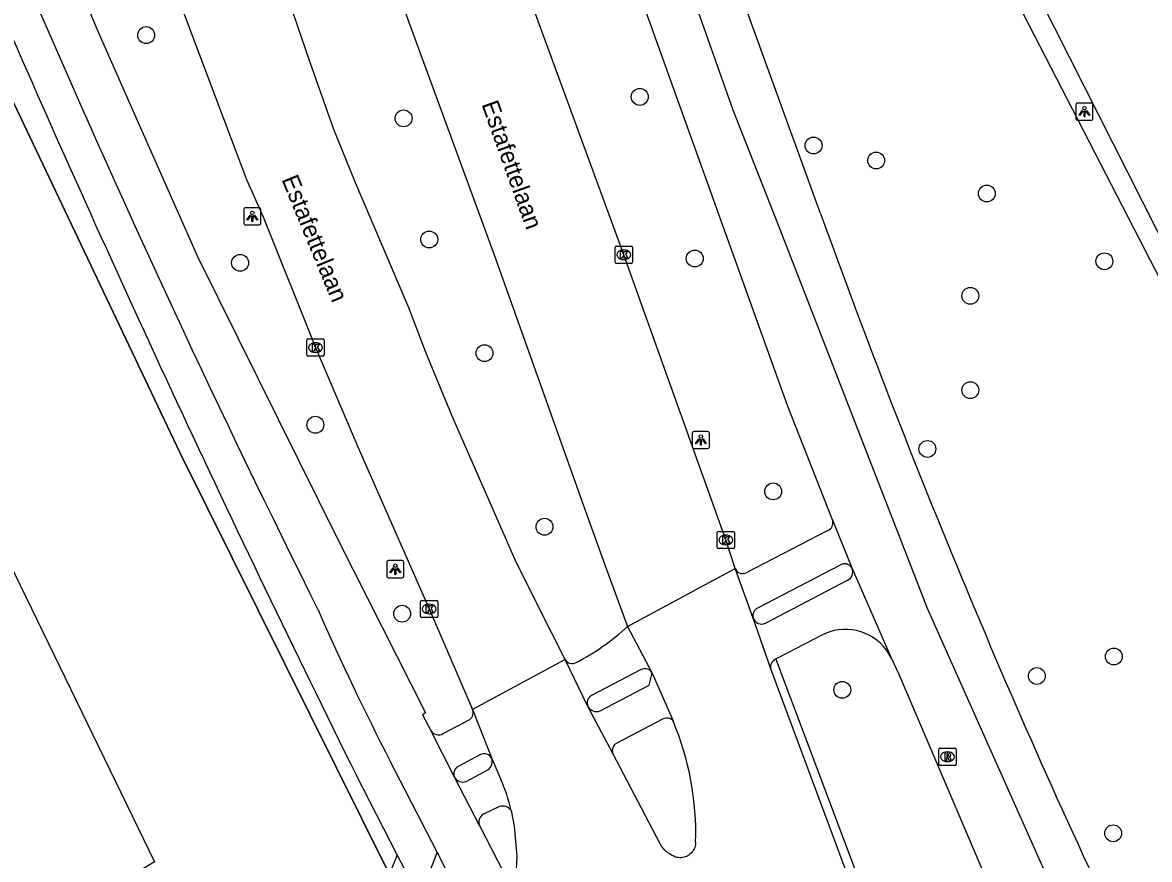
# Model space of a CAD drawing. Extents: x 158838 to 160074, y 386376 to 387776.
# Drawn here: x 159123.5 to 159188.9, y 387277.8 to 387326.4 of the extents above; entities that cross this region are included whole.
import ezdxf

# ---------------------------------------------------------------- set-up
doc = ezdxf.new("R2010")
doc.units = 0
for name, color, linetype in [('IMGEO_Berm_open', 7, 'Continuous'), ('IMGEO_Boom', 7, 'Continuous'), ('IMGEO_Fietspad_gesloten', 7, 'Continuous'), ('IMGEO_Fietspad_open', 7, 'Continuous'), ('IMGEO_Groenvoorziening', 7, 'Continuous'), ('IMGEO_Hek', 7, 'Continuous'), ('IMGEO_Kolk', 7, 'Continuous'), ('IMGEO_Lichtpunt', 7, 'Continuous'), ('IMGEO_Openbare_ruimte_label', 7, 'Continuous'), ('IMGEO_Pand', 7, 'Continuous'), ('IMGEO_Parkeervlak_open', 7, 'Continuous'), ('IMGEO_Rijbaan_lokaal_gesloten', 7, 'Continuous'), ('IMGEO_Rioolput', 7, 'Continuous'), ('IMGEO_Voetpad_open', 7, 'Continuous')]:
    doc.layers.add(name, color=color, linetype=linetype)

msp = doc.modelspace()

# ---------------------------------------------------------------- linework, layer by layer
at = {"layer": 'IMGEO_Berm_open'}
msp.add_lwpolyline([(159167.198, 387289.45), (159172.7, 387274.857), (159175.747, 387267.87), (159176.718, 387265.825)], dxfattribs=at)
at = {"layer": 'IMGEO_Boom'}
for centre in [(159130.664, 387325.65), (159159.305, 387322.064), (159145.602, 387320.82), (159169.392, 387319.247), (159173.022, 387318.377), (159179.442, 387316.459), (159147.091, 387313.791), (159162.497, 387312.694), (159136.116, 387312.438), (159186.266, 387312.53), (159178.486, 387310.527), (159150.299, 387307.198), (159178.485, 387305.053), (159140.484, 387303.049), (159175.995, 387301.643), (159167.05, 387299.183), (159153.779, 387297.133), (159145.522, 387292.089), (159186.812, 387289.608), (159182.349, 387288.476), (159171.057, 387287.673), (159186.773, 387279.351)]:
    msp.add_circle(centre, 0.489, dxfattribs=at)
at = {"layer": 'IMGEO_Fietspad_gesloten'}
for points in [[(159128.072, 387325.399), (159129.745, 387321.615), (159133.641, 387312.8), (159141.817, 387296.315), (159146.881, 387286.339), (159146.705, 387286.224), (159147.177, 387285.324)], [(159148.556, 387282.605), (159147.177, 387285.324)], [(159147.553, 387278.26), (159144.821, 387283.538)], [(159150.028, 387279.772), (159148.556, 387282.605)], [(159150.028, 387279.772), (159151.416, 387277.056)], [(159149.276, 387274.84), (159147.553, 387278.26)]]:
    msp.add_lwpolyline(points, dxfattribs=at)
for centre, radius, start, end in [((159873.922, 387646.377), 811.985, 201.113346, 203.284745), ((159777.701, 387609.871), 711.825, 203.409054, 206.499215), ((159287.82, 387357.075), 160.799, 203.76888, 207.21437)]:
    msp.add_arc(centre, radius, start, end, dxfattribs=at)
at = {"layer": 'IMGEO_Fietspad_open'}
for points in [[(159241.987, 387161.499), (159241.072, 387163.276), (159239.654, 387165.944), (159224.192, 387195.365), (159212.826, 387217.468), (159196.082, 387250), (159193.579, 387254.862), (159185.609, 387270.852), (159175.995, 387292.396), (159167.405, 387314.468), (159164.73, 387321.295), (159159.918, 387334.918), (159154.676, 387349.669), (159151.45, 387360.212), (159147.299, 387371.842)], [(159144.238, 387370.749), (159148.463, 387357.842), (159156.056, 387337.038), (159167.867, 387304.177), (159170.435, 387297.651), (159170.503, 387297.478)], [(159170.503, 387297.478), (159171.628, 387294.708)], [(159171.628, 387294.708), (159173.892, 387289.524)], [(159166.597, 387291.535), (159171.36, 387294.036)], [(159173.892, 387289.524), (159173.766, 387289.756), (159173.62, 387289.975), (159173.455, 387290.181), (159173.272, 387290.371), (159173.072, 387290.544), (159172.859, 387290.699), (159172.632, 387290.833), (159172.394, 387290.947), (159172.147, 387291.04), (159171.892, 387291.11), (159171.633, 387291.156), (159171.37, 387291.18), (159171.106, 387291.18), (159170.843, 387291.156), (159170.584, 387291.109), (159170.329, 387291.039), (159170.082, 387290.946), (159169.865, 387290.843), (159167.291, 387289.506), (159167.198, 387289.45)], [(159173.892, 387289.524), (159174.345, 387288.581), (159180.896, 387273.22), (159181.018, 387272.967), (159181.489, 387272.084), (159181.659, 387271.751)], [(159157.017, 387286.449), (159159.853, 387287.936), (159160.03, 387288.647)], [(159160.657, 387285.983), (159157.971, 387284.588)], [(159149.241, 387282.364), (159150.495, 387283.037)], [(159151.169, 387280.904), (159150.233, 387280.461)], [(159147.553, 387278.26), (159146.53, 387275.631)]]:
    msp.add_lwpolyline(points, dxfattribs=at)
for centre, radius, start, end in [((159171.144, 387294.512), 0.523, 294.46206, 22.05277), ((159166.38, 387292.005), 0.517, 200.20704, 294.76202), ((159167.356, 387289.014), 0.463, 109.88328, 195.85048), ((159156.814, 387287.018), 0.604, 210.6401, 289.61048), ((159160.878, 387285.576), 0.463, 39.13364, 118.43654), ((159158.231, 387284.136), 0.521, 119.88382, 197.58793), ((159150.174, 387283.511), 0.573, 304.08031, 18.26313), ((159149.039, 387282.885), 0.559, 210.07468, 291.15904), ((159150.494, 387280.008), 0.522, 119.94595, 206.91513), ((159151.351, 387280.344), 0.589, 34.67443, 108.04385)]:
    msp.add_arc(centre, radius, start, end, dxfattribs=at)
at = {"layer": 'IMGEO_Groenvoorziening'}
for points in [[(159224.36, 387402.222), (159224.03, 387402.865), (159159.729, 387369.196), (159208.786, 387274.075), (159201.998, 387269.928), (159255.258, 387166.205), (159257.42, 387167.319)], [(159271.465, 387305.683), (159209.686, 387274.058), (159161.319, 387369.689), (159224.36, 387402.222)]]:
    msp.add_lwpolyline(points, dxfattribs=at)
at = {"layer": 'IMGEO_Hek'}
for points in [[(159224.03, 387402.865), (159159.729, 387369.196), (159208.786, 387274.075), (159201.998, 387269.928), (159255.258, 387166.205), (159257.42, 387167.319)], [(159111.223, 387350.914), (159120.947, 387325.983), (159132.639, 387301.404), (159144.696, 387277.152), (159141.337, 387268.603), (159136.701, 387264.574), (159101.97, 387242.767)]]:
    msp.add_lwpolyline(points, dxfattribs=at)
at = {"layer": 'IMGEO_Kolk'}
for p, q in [((159157.877, 387312.485), (159157.877, 387313.337)), ((159157.952, 387313.411), (159158.804, 387313.411)), ((159158.365, 387313.191), (159158.39, 387313.191)), ((159158.878, 387313.337), (159158.878, 387312.485)), ((159158.388, 387312.631), (159158.363, 387312.631)), ((159158.804, 387312.411), (159157.952, 387312.411)), ((159139.992, 387307.1), (159139.992, 387307.952)), ((159140.067, 387308.026), (159140.919, 387308.026)), ((159140.993, 387307.952), (159140.993, 387307.1)), ((159140.48, 387307.806), (159140.505, 387307.806)), ((159140.919, 387307.026), (159140.067, 387307.026)), ((159140.503, 387307.246), (159140.478, 387307.246)), ((159163.798, 387295.94), (159163.798, 387296.792)), ((159163.873, 387296.866), (159164.725, 387296.866)), ((159164.799, 387296.792), (159164.799, 387295.94)), ((159164.286, 387296.646), (159164.311, 387296.646)), ((159164.725, 387295.866), (159163.873, 387295.866)), ((159164.309, 387296.086), (159164.284, 387296.086)), ((159146.583, 387291.935), (159146.583, 387292.787)), ((159146.658, 387292.861), (159147.51, 387292.861)), ((159147.071, 387292.641), (159147.096, 387292.641)), ((159147.584, 387292.787), (159147.584, 387291.935)), ((159147.51, 387291.861), (159146.658, 387291.861)), ((159147.094, 387292.081), (159147.069, 387292.081))]:
    msp.add_line(p, q, dxfattribs=at)
for points in [[(159157.877, 387312.485), (159157.877, 387313.337)], [(159157.952, 387313.411), (159158.804, 387313.411)], [(159158.878, 387313.337), (159158.878, 387312.485)], [(159158.198, 387313.111), (159158.321, 387313.111), (159158.321, 387312.96), (159158.451, 387313.111), (159158.615, 387313.111), (159158.469, 387312.96), (159158.622, 387312.711), (159158.47, 387312.711), (159158.385, 387312.875), (159158.321, 387312.808), (159158.321, 387312.711), (159158.198, 387312.711), (159158.198, 387313.111)], [(159158.804, 387312.411), (159157.952, 387312.411)], [(159139.992, 387307.1), (159139.992, 387307.952)], [(159140.067, 387308.026), (159140.919, 387308.026)], [(159140.993, 387307.952), (159140.993, 387307.1)], [(159140.313, 387307.726), (159140.436, 387307.726), (159140.436, 387307.575), (159140.566, 387307.726), (159140.73, 387307.726), (159140.584, 387307.575), (159140.737, 387307.326), (159140.585, 387307.326), (159140.5, 387307.49), (159140.436, 387307.423), (159140.436, 387307.326), (159140.313, 387307.326), (159140.313, 387307.726)], [(159140.919, 387307.026), (159140.067, 387307.026)], [(159163.798, 387295.94), (159163.798, 387296.792)], [(159163.873, 387296.866), (159164.725, 387296.866)], [(159164.799, 387296.792), (159164.799, 387295.94)], [(159164.119, 387296.566), (159164.242, 387296.566), (159164.242, 387296.415), (159164.372, 387296.566), (159164.536, 387296.566), (159164.39, 387296.415), (159164.543, 387296.166), (159164.391, 387296.166), (159164.306, 387296.33), (159164.242, 387296.263), (159164.242, 387296.166), (159164.119, 387296.166), (159164.119, 387296.566)], [(159164.725, 387295.866), (159163.873, 387295.866)], [(159146.583, 387291.935), (159146.583, 387292.787)], [(159146.658, 387292.861), (159147.51, 387292.861)], [(159146.904, 387292.561), (159147.027, 387292.561), (159147.027, 387292.41), (159147.157, 387292.561), (159147.321, 387292.561), (159147.175, 387292.41), (159147.328, 387292.161), (159147.176, 387292.161), (159147.091, 387292.325), (159147.027, 387292.258), (159147.027, 387292.161), (159146.904, 387292.161), (159146.904, 387292.561)], [(159147.584, 387292.787), (159147.584, 387291.935)], [(159147.51, 387291.861), (159146.658, 387291.861)]]:
    msp.add_lwpolyline(points, dxfattribs=at)
for centre, start, end in [((159157.954, 387313.335), 91.55205, 178.44795), ((159157.954, 387313.335), 91.55205, 178.44795), ((159158.802, 387313.335), 1.55205, 88.44795), ((159158.802, 387313.335), 1.55205, 88.44795), ((159157.954, 387312.487), 181.55205, 268.44795), ((159157.954, 387312.487), 181.55205, 268.44795), ((159158.802, 387312.487), 271.55205, 358.44795), ((159158.802, 387312.487), 271.55205, 358.44795), ((159140.069, 387307.95), 91.55205, 178.44795), ((159140.069, 387307.95), 91.55205, 178.44795), ((159140.917, 387307.95), 1.55205, 88.44795), ((159140.917, 387307.95), 1.55205, 88.44795), ((159140.069, 387307.102), 181.55205, 268.44795), ((159140.069, 387307.102), 181.55205, 268.44795), ((159140.917, 387307.102), 271.55205, 358.44795), ((159140.917, 387307.102), 271.55205, 358.44795), ((159163.875, 387296.79), 91.55205, 178.44795), ((159163.875, 387296.79), 91.55205, 178.44795), ((159164.723, 387296.79), 1.55205, 88.44795), ((159164.723, 387296.79), 1.55205, 88.44795), ((159163.875, 387295.942), 181.55205, 268.44795), ((159163.875, 387295.942), 181.55205, 268.44795), ((159164.723, 387295.942), 271.55205, 358.44795), ((159164.723, 387295.942), 271.55205, 358.44795), ((159146.66, 387292.785), 91.55205, 178.44795), ((159146.66, 387292.785), 91.55205, 178.44795), ((159147.508, 387292.785), 1.55205, 88.44795), ((159147.508, 387292.785), 1.55205, 88.44795), ((159146.66, 387291.937), 181.55205, 268.44795), ((159146.66, 387291.937), 181.55205, 268.44795), ((159147.508, 387291.937), 271.55205, 358.44795), ((159147.508, 387291.937), 271.55205, 358.44795)]:
    msp.add_arc(centre, 0.0765, start, end, dxfattribs=at)
for centre, major_axis, ratio, start_param, end_param in [((159158.364, 387312.911), (-0.387, 0.002), 0.722429, 4.712389, 7.853982), ((159158.389, 387312.911), (-0.39, 0.002), 0.717154, 1.570796, 4.712389), ((159140.479, 387307.526), (-0.387, 0.002), 0.722429, 4.712389, 7.853982), ((159140.504, 387307.526), (-0.39, 0.002), 0.717154, 1.570796, 4.712389), ((159164.285, 387296.366), (-0.387, 0.002), 0.722429, 4.712389, 7.853982), ((159164.31, 387296.366), (-0.39, 0.002), 0.717154, 1.570796, 4.712389), ((159147.07, 387292.361), (-0.387, 0.002), 0.722429, 4.712389, 7.853982), ((159147.095, 387292.361), (-0.39, 0.002), 0.717154, 1.570796, 4.712389)]:
    msp.add_ellipse(centre, major_axis=major_axis, ratio=ratio, start_param=start_param, end_param=end_param, dxfattribs=at)
at = {"layer": 'IMGEO_Lichtpunt'}
for p, q in [((159185.51, 387321.708), (159184.702, 387321.708)), ((159185.51, 387321.708), (159184.702, 387321.708)), ((159184.608, 387321.613), (159184.608, 387320.806)), ((159184.608, 387321.613), (159184.608, 387320.806)), ((159185.604, 387320.806), (159185.604, 387321.613)), ((159185.604, 387320.806), (159185.604, 387321.613)), ((159184.702, 387320.712), (159185.51, 387320.712)), ((159184.702, 387320.712), (159185.51, 387320.712)), ((159136.325, 387315.543), (159136.325, 387314.736)), ((159136.325, 387315.543), (159136.325, 387314.736)), ((159137.227, 387315.638), (159136.419, 387315.638)), ((159137.227, 387315.638), (159136.419, 387315.638)), ((159137.321, 387314.736), (159137.321, 387315.543)), ((159137.321, 387314.736), (159137.321, 387315.543)), ((159136.419, 387314.642), (159137.227, 387314.642)), ((159136.419, 387314.642), (159137.227, 387314.642)), ((159162.352, 387302.569), (159162.352, 387301.762)), ((159162.352, 387302.569), (159162.352, 387301.762)), ((159163.254, 387302.664), (159162.446, 387302.664)), ((159163.254, 387302.664), (159162.446, 387302.664)), ((159163.348, 387301.762), (159163.348, 387302.569)), ((159163.348, 387301.762), (159163.348, 387302.569)), ((159162.446, 387301.668), (159163.254, 387301.668)), ((159162.446, 387301.668), (159163.254, 387301.668)), ((159144.625, 387295.077), (159144.625, 387294.27)), ((159144.625, 387295.077), (159144.625, 387294.27)), ((159145.527, 387295.172), (159144.719, 387295.172)), ((159145.527, 387295.172), (159144.719, 387295.172)), ((159145.621, 387294.27), (159145.621, 387295.077)), ((159145.621, 387294.27), (159145.621, 387295.077)), ((159144.719, 387294.176), (159145.527, 387294.176)), ((159144.719, 387294.176), (159145.527, 387294.176))]:
    msp.add_line(p, q, dxfattribs=at)
for points in [[(159184.982, 387321.277), (159185.021, 387321.249), (159184.833, 387320.987), (159184.795, 387321.014), (159184.982, 387321.277)], [(159185.084, 387321.229), (159185.131, 387321.229), (159185.131, 387320.907), (159185.084, 387320.907), (159185.084, 387321.229)], [(159185.194, 387321.249), (159185.232, 387321.276), (159185.419, 387321.014), (159185.38, 387320.986), (159185.194, 387321.249)], [(159136.699, 387315.207), (159136.738, 387315.179), (159136.55, 387314.917), (159136.512, 387314.944), (159136.699, 387315.207)], [(159136.801, 387315.159), (159136.848, 387315.159), (159136.848, 387314.837), (159136.801, 387314.837), (159136.801, 387315.159)], [(159136.911, 387315.179), (159136.949, 387315.206), (159137.136, 387314.944), (159137.097, 387314.916), (159136.911, 387315.179)], [(159162.726, 387302.233), (159162.765, 387302.205), (159162.577, 387301.943), (159162.539, 387301.97), (159162.726, 387302.233)], [(159162.828, 387302.185), (159162.875, 387302.185), (159162.875, 387301.863), (159162.828, 387301.863), (159162.828, 387302.185)], [(159162.938, 387302.205), (159162.976, 387302.232), (159163.163, 387301.97), (159163.124, 387301.942), (159162.938, 387302.205)], [(159144.999, 387294.741), (159145.038, 387294.713), (159144.85, 387294.451), (159144.812, 387294.478), (159144.999, 387294.741)], [(159145.101, 387294.693), (159145.148, 387294.693), (159145.148, 387294.371), (159145.101, 387294.371), (159145.101, 387294.693)], [(159145.211, 387294.713), (159145.249, 387294.74), (159145.436, 387294.478), (159145.397, 387294.45), (159145.211, 387294.713)]]:
    msp.add_lwpolyline(points, dxfattribs=at)
for centre in [(159185.107, 387321.411), (159136.824, 387315.341), (159162.851, 387302.367), (159145.124, 387294.875)]:
    msp.add_circle(centre, 0.0994, dxfattribs=at)
for centre, start, end in [((159184.702, 387321.613), 90, 180), ((159184.702, 387321.613), 90, 180), ((159185.51, 387321.613), 0, 90), ((159185.51, 387321.613), 0, 90), ((159184.702, 387320.806), 180, 270), ((159184.702, 387320.806), 180, 270), ((159185.51, 387320.806), 270, 0), ((159185.51, 387320.806), 270, 360), ((159136.419, 387315.543), 90, 180), ((159136.419, 387315.543), 90, 180), ((159137.227, 387315.543), 0, 90), ((159137.227, 387315.543), 0, 90), ((159136.419, 387314.736), 180, 270), ((159136.419, 387314.736), 180, 270), ((159137.227, 387314.736), 270, 0), ((159137.227, 387314.736), 270, 360), ((159162.446, 387302.569), 90, 180), ((159162.446, 387302.569), 90, 180), ((159163.254, 387302.569), 0, 90), ((159163.254, 387302.569), 0, 90), ((159162.446, 387301.762), 180, 270), ((159162.446, 387301.762), 180, 270), ((159163.254, 387301.762), 270, 0), ((159163.254, 387301.762), 270, 360), ((159144.719, 387295.077), 90, 180), ((159144.719, 387295.077), 90, 180), ((159145.527, 387295.077), 0, 90), ((159145.527, 387295.077), 0, 90), ((159144.719, 387294.27), 180, 270), ((159144.719, 387294.27), 180, 270), ((159145.527, 387294.27), 270, 0), ((159145.527, 387294.27), 270, 360)]:
    msp.add_arc(centre, 0.0946, start, end, dxfattribs=at)
at = {"layer": 'IMGEO_Pand'}
msp.add_lwpolyline([(159119.127, 387302.434), (159131.157, 387277.704), (159091.538, 387253.454), (159070.581, 387287.744), (159058.345, 387280.343), (159050.694, 387292.811), (159083.08, 387312.609)], dxfattribs=at)
at = {"layer": 'IMGEO_Parkeervlak_open'}
msp.add_lwpolyline([(159134.852, 387263.413), (159136.701, 387264.574), (159141.337, 387268.603), (159144.696, 387277.152), (159132.639, 387301.404), (159120.947, 387325.983), (159111.223, 387350.914)], dxfattribs=at)
at = {"layer": 'IMGEO_Rijbaan_lokaal_gesloten'}
for points in [[(159164.848, 387294.711), (159164.298, 387296.365), (159158.378, 387312.911), (159150.713, 387333.864), (159144.707, 387350.791), (159144.21, 387352.481), (159139.278, 387366.374), (159139.083, 387366.881), (159138.782, 387367.789)], [(159132.448, 387364.417), (159136.437, 387353.085), (159144.422, 387330.486), (159150.85, 387312.913), (159156.261, 387297.757), (159157.279, 387294.926), (159158.592, 387291.342)], [(159154.981, 387289.43), (159153.393, 387292.563), (159152.056, 387295.257), (159151.24, 387297.113), (159148.417, 387303.552), (159146.881, 387307.292), (159145.903, 387309.831), (159142.765, 387317.172), (159141.55, 387320.179), (159140.175, 387324.063), (159137.281, 387332.542), (159135.452, 387337.856), (159131.485, 387349.001), (159127.145, 387361.276)], [(159121.345, 387357.917), (159121.86, 387356.708), (159132.418, 387328.045), (159132.922, 387326.705), (159136.497, 387317.277), (159137.458, 387315.111), (159140.494, 387307.527), (159142.943, 387301.769), (159147.085, 387292.362), (159149.373, 387287.073), (159149.608, 387286.535)], [(159158.592, 387291.342), (159164.848, 387294.711)], [(159165.895, 387291.826), (159164.848, 387294.711)], [(159166.91, 387288.888), (159165.895, 387291.826)], [(159158.592, 387291.342), (159160.03, 387288.647)], [(159154.981, 387289.43), (159149.608, 387286.535)], [(159156.295, 387286.71), (159154.981, 387289.43)], [(159160.03, 387288.647), (159161.237, 387285.868)], [(159176.015, 387266.004), (159175.242, 387267.631), (159172.216, 387274.661), (159166.91, 387288.888)], [(159149.608, 387286.535), (159150.718, 387283.691)], [(159157.734, 387283.979), (159156.295, 387286.71)], [(159162.549, 387278.835), (159162.546, 387278.771), (159162.537, 387278.691), (159162.52, 387278.611), (159162.496, 387278.534), (159162.465, 387278.459), (159162.428, 387278.388), (159162.385, 387278.32), (159162.335, 387278.256), (159162.28, 387278.196), (159162.22, 387278.142), (159162.156, 387278.093), (159162.087, 387278.051), (159162.015, 387278.014), (159161.94, 387277.985), (159161.862, 387277.962), (159161.783, 387277.946), (159161.703, 387277.937), (159161.622, 387277.936), (159161.541, 387277.941), (159161.461, 387277.954), (159161.383, 387277.974), (159161.276, 387278.019), (159161.138, 387278.089), (159161.006, 387278.172), (159160.883, 387278.266), (159160.768, 387278.371), (159160.664, 387278.486), (159160.57, 387278.61), (159160.487, 387278.741), (159157.734, 387283.979)], [(159150.718, 387283.691), (159151.236, 387282.48)], [(159151.836, 387280.679), (159152.026, 387279.759), (159152.171, 387278.034), (159152.119, 387276.895)]]:
    msp.add_lwpolyline(points, dxfattribs=at)
for centre, radius, start, end in [((159145.809, 387279.351), 16.748, 358.23415, 22.89989), ((159143.588, 387278.932), 8.431, 11.96107, 24.88974)]:
    msp.add_arc(centre, radius, start, end, dxfattribs=at)
at = {"layer": 'IMGEO_Rioolput'}
for p, q in [((159176.662, 387283.365), (159176.662, 387284.217)), ((159176.737, 387284.291), (159177.589, 387284.291)), ((159177.15, 387284.071), (159177.175, 387284.071)), ((159177.663, 387284.217), (159177.663, 387283.365)), ((159177.589, 387283.291), (159176.737, 387283.291)), ((159177.173, 387283.511), (159177.148, 387283.511))]:
    msp.add_line(p, q, dxfattribs=at)
for points in [[(159176.662, 387283.365), (159176.662, 387284.217)], [(159176.737, 387284.291), (159177.589, 387284.291)], [(159177.251, 387283.989), (159176.999, 387283.991), (159176.999, 387283.591)], [(159176.999, 387283.591), (159177.123, 387283.591), (159177.123, 387283.753), (159177.134, 387283.753)], [(159177.177, 387283.91), (159177.123, 387283.91), (159177.123, 387283.829)], [(159177.123, 387283.829), (159177.175, 387283.829)], [(159177.181, 387283.724), (159177.252, 387283.591), (159177.392, 387283.591), (159177.327, 387283.717)], [(159177.663, 387284.217), (159177.663, 387283.365)], [(159177.589, 387283.291), (159176.737, 387283.291)]]:
    msp.add_lwpolyline(points, dxfattribs=at)
for centre, radius, start, end in [((159176.739, 387284.215), 0.0765, 91.55205, 178.44795), ((159176.739, 387284.215), 0.0765, 91.55205, 178.44795), ((159177.133, 387283.7), 0.0533, 26.02933, 88.69889), ((159177.159, 387284.018), 0.19, 274.7715, 282.96867), ((159177.183, 387283.814), 0.0964, 77.00612, 93.18647), ((159177.197, 387283.871), 0.0378, 276.66336, 79.67722), ((159177.25, 387283.879), 0.109, 350.36119, 89.41601), ((159177.248, 387283.879), 0.112, 277.58423, 350.98172), ((159177.232, 387283.664), 0.108, 29.51342, 73.79051), ((159177.587, 387284.215), 0.0765, 1.55205, 88.44795), ((159177.587, 387284.215), 0.0765, 1.55205, 88.44795), ((159176.739, 387283.367), 0.0765, 181.55205, 268.44795), ((159176.739, 387283.367), 0.0765, 181.55205, 268.44795), ((159177.587, 387283.367), 0.0765, 271.55205, 358.44795), ((159177.587, 387283.367), 0.0765, 271.55205, 358.44795)]:
    msp.add_arc(centre, radius, start, end, dxfattribs=at)
for centre, major_axis, ratio, start_param, end_param in [((159177.149, 387283.791), (-0.387, 0.002), 0.722429, 4.712389, 7.853982), ((159177.174, 387283.791), (-0.39, 0.002), 0.717154, 1.570796, 4.712389)]:
    msp.add_ellipse(centre, major_axis=major_axis, ratio=ratio, start_param=start_param, end_param=end_param, dxfattribs=at)
at = {"layer": 'IMGEO_Voetpad_open'}
for points in [[(159169.799, 387315.299), (159157.013, 387350.501), (159152.273, 387364.229), (159149.084, 387373.132), (159148.676, 387374.273)], [(159170.22, 387296.923), (159165.521, 387294.481)], [(159171.628, 387294.708), (159171.607, 387294.746), (159171.583, 387294.783), (159171.556, 387294.817), (159171.525, 387294.848), (159171.492, 387294.877), (159171.457, 387294.902), (159171.419, 387294.925), (159171.38, 387294.943), (159171.339, 387294.959), (159171.297, 387294.97), (159171.254, 387294.978), (159171.211, 387294.982), (159171.167, 387294.982), (159171.124, 387294.978), (159171.081, 387294.97), (159171.038, 387294.958), (159170.998, 387294.943), (159170.958, 387294.924), (159170.932, 387294.909), (159166.178, 387292.428), (159166.138, 387292.41), (159166.1, 387292.389), (159166.064, 387292.364), (159166.031, 387292.336), (159166, 387292.305), (159165.972, 387292.272), (159165.947, 387292.236), (159165.925, 387292.198), (159165.907, 387292.159), (159165.893, 387292.117), (159165.882, 387292.075), (159165.875, 387292.032), (159165.872, 387291.989), (159165.873, 387291.945), (159165.877, 387291.902), (159165.886, 387291.859), (159165.895, 387291.826)], [(159159.358, 387288.839), (159156.509, 387287.34)], [(159147.898, 387285.132), (159149.453, 387285.958)], [(159150.061, 387283.916), (159148.804, 387283.252)], [(159145.224, 387278.105), (159142.85, 387282.736)], [(159145.224, 387278.105), (159144.543, 387276.371), (159141.753, 387269.037), (159141.523, 387268.433)], [(159146.53, 387275.631), (159145.224, 387278.105)]]:
    msp.add_lwpolyline(points, dxfattribs=at)
for centre, radius, start, end in [((160017.567, 387716.767), 976.48, 203.570188, 206.390425), ((159600.963, 387470.364), 458.2, 199.7808, 202.69526), ((159170.049, 387297.36), 0.469, 291.39402, 14.57101), ((159165.284, 387294.887), 0.47, 201.96054, 300.30339), ((159567.378, 387454.749), 421.194, 202.49829, 205.70781), ((159149.531, 387301.151), 13.354, 297.06329, 312.72729), ((159155.375, 387289.644), 0.448, 208.48432, 301.12939), ((159159.595, 387288.396), 0.502, 29.97109, 118.13812), ((159156.76, 387286.903), 0.504, 119.88826, 202.58828), ((159149.126, 387286.355), 0.514, 309.44078, 20.48635), ((159147.634, 387285.59), 0.529, 210.18833, 299.98841), ((159150.277, 387283.476), 0.49, 25.98967, 116.20118), ((159149.011, 387282.802), 0.495, 114.64303, 203.41255)]:
    msp.add_arc(centre, radius, start, end, dxfattribs=at)

# ---------------------------------------------------------------- texts
at = {"layer": 'IMGEO_Openbare_ruimte_label'}
for rotation, p in [(289.68464, (159150.114, 387321.642)), (292.38637, (159138.507, 387317.284))]:
    msp.add_text('Estafettelaan', height=1, rotation=rotation, dxfattribs=at).set_placement(p)

doc.saveas('drawing.dxf')
